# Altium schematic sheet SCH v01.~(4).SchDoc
size A3; SheetNumber: 1; SheetTotal: 1
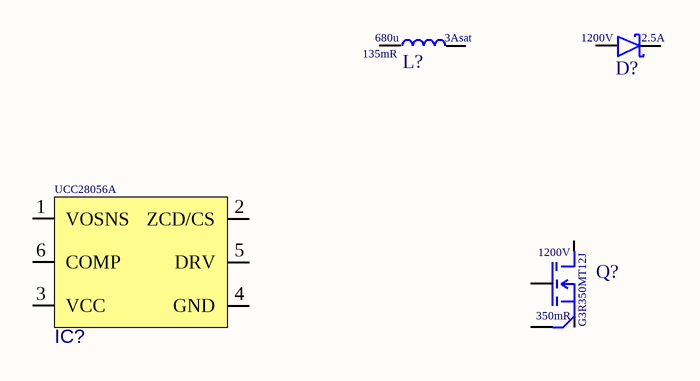
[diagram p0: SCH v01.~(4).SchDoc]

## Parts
D?  Forward Current: 2.5A  Reverse Voltage: 1200V  [DO-214-2]  (hidden comment: Diode Schottky)
IC?  UCC28056A  [SOT-23-6]
L?  Resistance: 135mR  Saturation current: 3Asat  Inductance: 680u  [60B684C]  (hidden comment: Inductor)
Q?  Manufacturer Part Number: G3R350MT12J  Rds: 350mR  Voltage: 1200V  [TO-263-7 D2PAK]  (hidden comment: Nmos_KS)

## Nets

Not connected (* = marked no-connect by the designer): D? A K; IC? 1(VOSNS) 2(ZCD/CS) 3(VCC) 4(GND) 5(DRV) 6(COMP); L? 1 2; Q? D G KS S

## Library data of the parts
D? = Diode Schottky: General Schottky Diode symbol; Manufacturer: GenerSiC; Manufacturer Part Number: GB01SLT12-214
IC? = UCC28056A: PFC TM IC; Manufacturer: Texas Instruments
L? = Inductor: Generic Inductor symbol; Manufacturer: Murata
Q? = Nmos_KS: Generic Nmos symbol with Kelvin Source; Manufacturer: GeneSiC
